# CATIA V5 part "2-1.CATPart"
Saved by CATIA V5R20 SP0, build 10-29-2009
Part number: 2
Material "Steel": density 7860 kg/m3, Young's modulus 2e+11 Pa, Poisson ratio 0.266, thermal expansion 1.17e-05 1/K
Bounding box of the stored display mesh (mm): x -20 to 20, y -9.249 to 9.249, z -2 to 21.155
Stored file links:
  E:\Ehsan\Amoozesh\CATIA\CATIA Course\Advanced\Videos\Session-17\2-1.CATPart
  D:\CATIA V5R20\B20\intel_a\startup\materials\Catalog.CATMaterial
  E:\Ehsan\Amoozesh\CATIA\CATIA Course\Advanced\Videos\Session-17\Product1.CATProduct
  D:\CATIA V5R20\B20\intel_a\resources\graphic\figures\CATIA_EnvironmentMap_DSRed_512x512.jpg
  D:\CATIA V5R20\B20\intel_a\resources\graphic\figures\CATIA_EnvironmentMap_DSBrown_512x512.jpg
  D:\CATIA V5R20\B20\intel_a\resources\graphic\figures\CATIA_EnvironmentMap_DSGreen_512x512.jpg
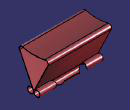
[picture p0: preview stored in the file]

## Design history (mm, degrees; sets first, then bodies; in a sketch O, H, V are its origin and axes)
SheetMetalParameters1: Thickness 0.25, BendRadius 0.5, KFactor 0.400515 {= log(min(100,max(20*SheetMetalParameters1.BendRadius,SheetMetalParameters1.Thickness)/SheetMetalParameters1.Thickness))/log(100)/2}, ReliefRadialLength 1, ReliefAxialLength 2, MinimumBendRadius 0
AxisSystem1: origin (0, 0, 0), X (1, 0, 0), Y (0, 1, 0), Z (0, 0, 1)
Set1
  Plane1: stored without definition
Body1 (main body), material "Steel"
  Sketch1 on YZ plane of AxisSystem1, origin (0, 0, 0), H (0, 1, 0), V (0, 0, 1)
    line L1 (8.8503, 18.7526) -> (0.1996, 0.871)
    point P1 (0.1996, 0.871)
    arc A1 centre (2, 0) radius 2 from (0.1996, 0.871) to (0.8463, 1.6337) ccw
    point P2 (2, 0)
    point P3 (0.8463, 1.6337)
    arc A2 centre (0, 50) radius 30 from (7.1429, 20.8627) to (-7.1429, 20.8627) cw
    point P5 (-7.1429, 20.8627)
    arc A3 centre (7.5, 19.4059) radius 1.5 from (7.1429, 20.8627) to (8.8503, 18.7526) cw
    point P6 (7.1429, 20.8627)
    point P7 (8.8503, 18.7526)
    point P8 (7.5, 19.4059)
    point P9 (-0.1996, 0.871)
    point P10 (-8.8503, 18.7526)
    line L2 (-8.8503, 18.7526) -> (-0.1996, 0.871)
    point P11 (-7.1429, 20.8627)
    point P12 (-7.5, 19.4059)
    arc A4 centre (-7.5, 19.4059) radius 1.5 from (-7.1429, 20.8627) to (-8.8503, 18.7526) ccw
    radius A3 = 1.5
    distance A2 H = 20
    radius A1 = 2
    radius A2 = 30
    distance P12 P8 = 15
    distance P3 L1 = 0.25
    tangency: A1 L1, A3 A2, A3 L1, A1 V
    coincidence: P2 H, P5 P11
    symmetry: P1 P9 V, P7 P10 V, L1 L2 V, P6 P11 V, A3 A4 V
  d_Extrusion1: Extrude_Thickness 0.25, Extrude_Profile Sketch1, Extrude_StartLength 20, Extrude_EndLength 20, Extrude_Radius 0.5, Extrude_DeductionTable SheetMetalParameters1, Extrude_FixedPoint Sketch1.P1, KFacteur 0.400515 {= log(min(100,max(20*SheetMetalParameters1.BendRadius,SheetMetalParameters1.Thickness)/SheetMetalParameters1.Thickness))/log(100)/2}
  Sketch2 on yz-plane, origin (0, 0, 0), H (0, 1, 0), V (0, 0, 1)
    projected arc E1 centre (2, 0) radius 2 from (0.1996, 0.871) to (0.8463, 1.6337) ccw from sketch element
  Flange1: Guide edge [face of d_Extrusion1 | face of d_Extrusion1], KFacteur 0.400515 {= SheetMetalParameters1.KFactor}
  SHM_Mirror1: MirroringPlane zx-plane, ObjectToMirror Flange1
  CutOut1: Direction Sketch3, EndLimit through (limit type 2), Orientation true, Profile Sketch3, StartLimit through (limit type 2)
  SHM_Mirror2: MirroringPlane Plane1, ObjectToMirror CutOut1
  Sketch3 on face of Flange1, origin (0, 0.0454, -0.0219), H (-1, 0, 0), V (0, 0.4355, 0.9002)
    point P1 (13.2688, -28.3572)
    point P2 (-13.2688, -28.3572)
    projected line E1 (20, -9.8187) -> (-20, -9.8187) from edge [face of Flange1 | face of Flange1]
    projected line E2 (10, -9.8187) -> (-10, -9.8187) from edge [face of Flange1 | face of Flange1]
    construction line L1 (6.1431, -6.7134) -> (10.75, -1.129)
    point P6 (10.75, -1.129)
    line L2 (4.8003, -5.4383) -> (9.1802, 0.1102)
    line L3 (12.3198, -2.3682) -> (9.6274, -5.779)
    arc A1 centre (10.75, -1.129) radius 2 from (9.1802, 0.1102) to (12.3198, -2.3682) cw
    point P7 (9.1802, 0.1102)
    point P8 (12.3198, -2.3682)
    line L4 (9.4276, -6.5722) -> (10, -9.8187)
    point P9 (10, -9.8187)
    point P10 (6.9902, -2.6641)
    point P11 (9.3497, -6.1308)
    line L5 (4.0154, -5.8187) -> (-4.0154, -5.8187)
    point P12 (4.5, -5.8187)
    point P13 (5.7152, -3.1173)
    point P14 (-9.3497, -6.1308)
    point P15 (-10, -9.8187)
    point P16 (-12.3198, -2.3682)
    point P17 (-9.1802, 0.1102)
    line L6 (-9.4276, -6.5722) -> (-10, -9.8187)
    point P18 (-10.75, -1.129)
    arc A2 centre (-10.75, -1.129) radius 2 from (-9.1802, 0.1102) to (-12.3198, -2.3682) ccw
    line L7 (-12.3198, -2.3682) -> (-9.6274, -5.779)
    line L8 (-4.8003, -5.4383) -> (-9.1802, 0.1102)
    point P19 (-4.5, -5.8187)
    arc A3 centre (10.4124, -6.3986) radius 1 from (9.6274, -5.779) to (9.4276, -6.5722) ccw
    arc A4 centre (4.0154, -4.8187) radius 1 from (4.8003, -5.4383) to (4.0154, -5.8187) cw
    arc A5 centre (-10.4124, -6.3986) radius 1 from (-9.4276, -6.5722) to (-9.6274, -5.779) ccw
    arc A6 centre (-4.0154, -4.8187) radius 1 from (-4.0154, -5.8187) to (-4.8003, -5.4383) cw
    reference projected line E3 (20, 0.871) -> (-20, 0.871) from edge [face of d_Extrusion1 | face of Flange1]
    distance L2 L3 = 4
    distance L5 E1 = 4
    angle L4 E1 = 80
    distance P6 P18 = 21.5
    distance P9 P15 = 20
    radius A3 = 1
    distance P12 P19 = 9
    radius A4 = 1 {= Sketch3.radius(A3)}
    radius A5 = 1 {= Sketch3.radius(A3)}
    radius A6 = 1 {= Sketch3.radius(A3)}
    symmetry: P1 P2 V, P11 P14 V, P9 P15 V, P8 P16 V, P7 P17 V, L4 L6 V, A1 A2 V, L3 L7 V, L2 L8 V
    tangency: A1 L2, A1 L3, A3 L3, A3 L4, A4 L2, A4 L5, A5 L6, A5 L7, A6 L5, A6 L8, A1 E3
    coincidence: P9 E1, L3 P11, L4 P11, L2 P12, L5 P12, L6 P14, L7 P14, L5 P19, L8 P19
    midpoint: P10 L2
    horizontal: L5 H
